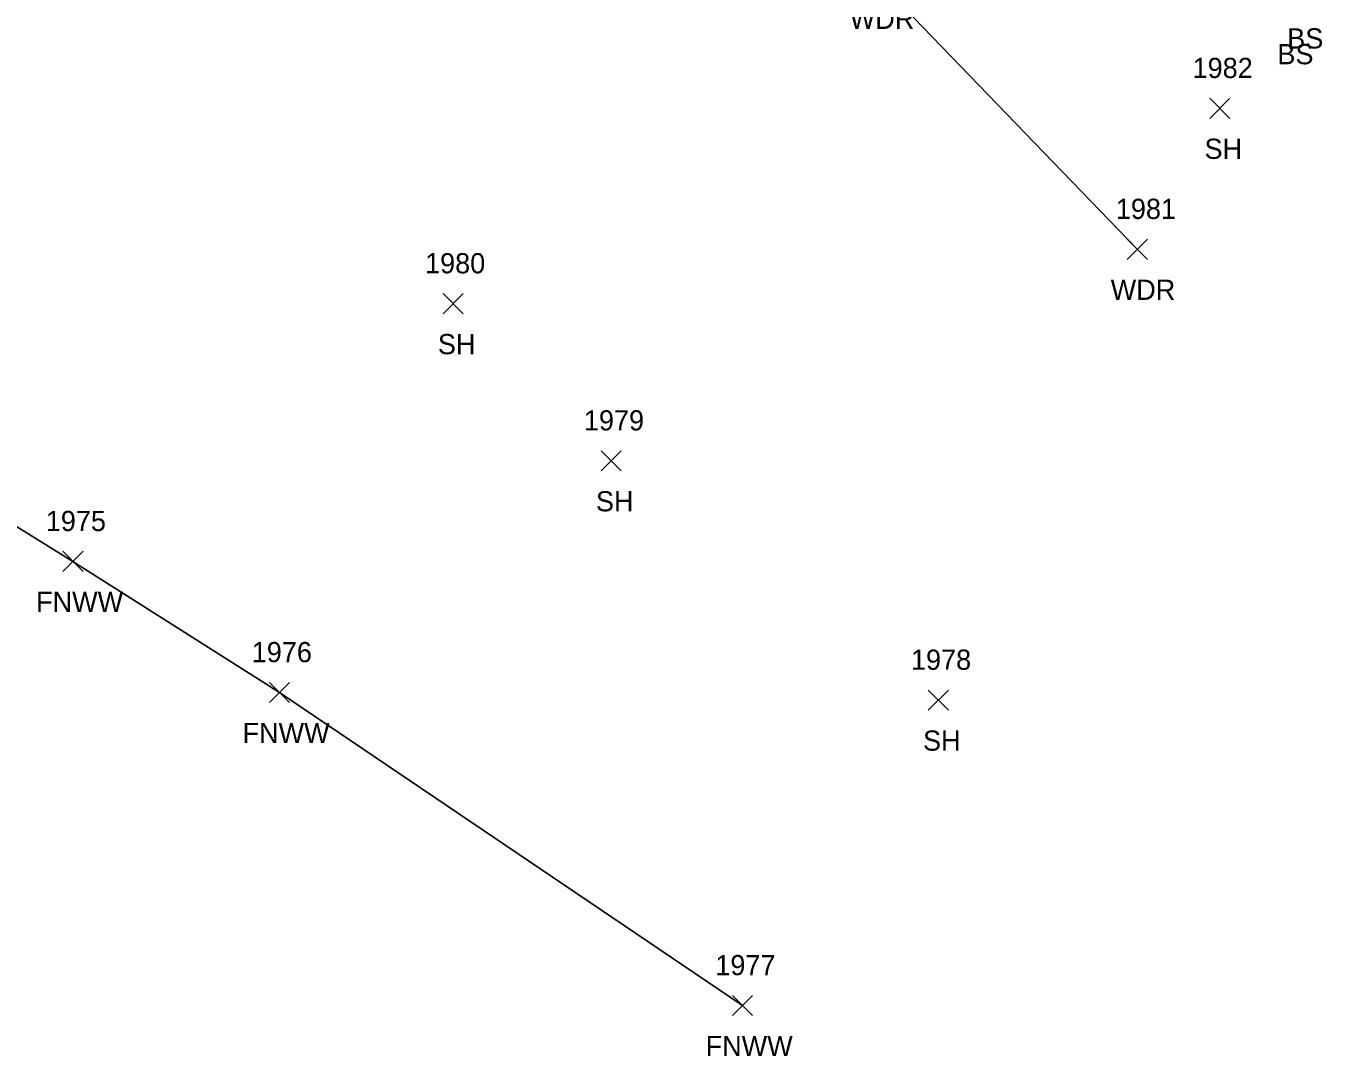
# Model space of a CAD drawing. Extents: x 1629176 to 1637209, y 606063 to 610167.
# Drawn here: x 1630613 to 1630741.2, y 606421.8 to 606523.7 of the extents above; entities that cross this region are included whole.
import ezdxf

# ---------------------------------------------------------------- set-up
doc = ezdxf.new("R2010")
doc.units = 0
for name, color, linetype in [('L_A', 7, 'Continuous'), ('L_I', 7, 'Continuous'), ('L_TIC', 7, 'Continuous'), ('LAWA', 7, 'Continuous'), ('LFNC', 7, 'Continuous')]:
    doc.layers.add(name, color=color, linetype=linetype)

msp = doc.modelspace()

# ---------------------------------------------------------------- linework, layer by layer
at = {"layer": 'L_TIC'}
for points in [[(1630730.04, 606514.52), (1630732.04, 606516.52)], [(1630732.04, 606514.52), (1630730.04, 606516.52)], [(1630721.88, 606500.58), (1630723.88, 606502.58)], [(1630723.88, 606500.58), (1630721.88, 606502.58)], [(1630654.22, 606495.2), (1630656.22, 606497.2)], [(1630656.22, 606495.2), (1630654.22, 606497.2)], [(1630669.85, 606479.66), (1630671.85, 606481.66)], [(1630671.85, 606479.66), (1630669.85, 606481.66)], [(1630616.62, 606469.71), (1630618.62, 606471.71)], [(1630618.62, 606469.71), (1630616.62, 606471.71)], [(1630637.04, 606456.74), (1630639.04, 606458.74)], [(1630639.04, 606456.74), (1630637.04, 606458.74)], [(1630702.2, 606455.99), (1630704.2, 606457.99)], [(1630704.2, 606455.99), (1630702.2, 606457.99)], [(1630682.84, 606425.78), (1630684.84, 606427.78)], [(1630684.84, 606425.78), (1630682.84, 606427.78)]]:
    msp.add_lwpolyline(points, dxfattribs=at)
at = {"layer": 'LAWA'}
msp.add_lwpolyline([(1630297.68, 606682.91), (1630335.71, 606675.48), (1630386.4, 606666.36), (1630422.65, 606653.68), (1630444.38, 606639.08), (1630446.66, 606637.81), (1630486.16, 606613.28), (1630514.89, 606608.05), (1630539.89, 606609.62), (1630562.09, 606603.08), (1630591.48, 606594.03), (1630626, 606578), (1630626.04, 606578.1), (1630670.33, 606553.73), (1630697.07, 606528.38), (1630722.88, 606501.58)], dxfattribs=at)
at = {"layer": 'LFNC'}
msp.add_lwpolyline([(1630083.24, 606643.38), (1630104.82, 606668.58), (1630132.44, 606699.6), (1630148.03, 606717.8), (1630178.45, 606705.28), (1630206.32, 606692.67), (1630267, 606665.5), (1630297.13, 606649.31), (1630336.07, 606632.29), (1630377.56, 606610.95), (1630421.19, 606588.3), (1630449.11, 606572.58), (1630476.9, 606556.84), (1630504.46, 606540.78), (1630518.72, 606532.31), (1630544.56, 606516.77), (1630586.07, 606490.29), (1630617.62, 606470.71), (1630638.04, 606457.74), (1630683.84, 606426.78)], dxfattribs=at)

# ---------------------------------------------------------------- texts
at = {"layer": 'L_A'}
for s, p in [('WDR', (1630694.44, 606523.38)), ('BS', (1630737.71, 606521.44)), ('BS', (1630736.74, 606519.88)), ('SH', (1630729.53, 606510.52)), ('WDR', (1630720.25, 606496.58)), ('SH', (1630653.71, 606491.2)), ('SH', (1630669.34, 606475.66)), ('FNWW', (1630613.97, 606465.71)), ('FNWW', (1630634.39, 606452.74)), ('SH', (1630701.69, 606451.99)), ('FNWW', (1630680.19, 606421.78))]:
    msp.add_text(s, height=2, dxfattribs=at).set_placement(p)
at = {"layer": 'L_I'}
for s, p in [('1982', (1630728.35, 606518.52)), ('1981', (1630720.76, 606504.58)), ('1980', (1630652.44, 606499.2)), ('1979', (1630668.15, 606483.66)), ('1975', (1630614.93, 606473.71)), ('1976', (1630635.3, 606460.74)), ('1978', (1630700.5, 606459.99)), ('1977', (1630681.15, 606429.78))]:
    msp.add_text(s, height=2, dxfattribs=at).set_placement(p)

doc.saveas('drawing.dxf')
